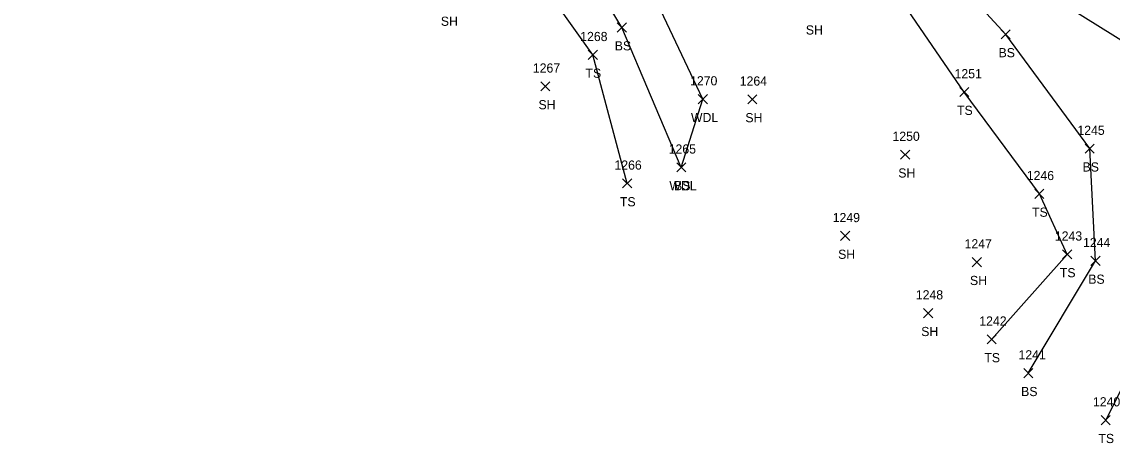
# Model space of a CAD drawing. Extents: x 1537342 to 1542195, y 163002 to 168596.
# Drawn here: x 1541701.1 to 1541938.8, y 163108.8 to 163200.7 of the extents above; entities that cross this region are included whole.
import ezdxf

# ---------------------------------------------------------------- set-up
doc = ezdxf.new("R2010")
doc.units = 0
for name, color, linetype in [('L_A', 7, 'Continuous'), ('L_I', 7, 'Continuous'), ('L_TIC', 7, 'Continuous'), ('LAWA', 7, 'Continuous'), ('LELB', 7, 'Continuous')]:
    doc.layers.add(name, color=color, linetype=linetype)

msp = doc.modelspace()

# ---------------------------------------------------------------- linework, layer by layer
at = {"layer": 'L_TIC'}
for points in [[(1541830.91, 163198.44), (1541832.91, 163200.44)], [(1541832.91, 163198.44), (1541830.91, 163200.44)], [(1541914.6, 163196.94), (1541916.6, 163198.94)], [(1541916.6, 163196.94), (1541914.6, 163198.94)], [(1541824.57, 163192.47), (1541826.57, 163194.47)], [(1541826.57, 163192.47), (1541824.57, 163194.47)], [(1541814.24, 163185.6), (1541816.24, 163187.6)], [(1541816.24, 163185.6), (1541814.24, 163187.6)], [(1541848.55, 163182.81), (1541850.55, 163184.81)], [(1541850.55, 163182.81), (1541848.55, 163184.81)], [(1541859.35, 163182.77), (1541861.35, 163184.77)], [(1541861.35, 163182.77), (1541859.35, 163184.77)], [(1541905.57, 163184.36), (1541907.57, 163186.36)], [(1541907.57, 163184.36), (1541905.57, 163186.36)], [(1541932.92, 163172.02), (1541934.92, 163174.02)], [(1541934.92, 163172.02), (1541932.92, 163174.02)], [(1541892.69, 163170.71), (1541894.69, 163172.71)], [(1541894.69, 163170.71), (1541892.69, 163172.71)], [(1541843.86, 163167.93), (1541845.86, 163169.93)], [(1541845.86, 163167.93), (1541843.86, 163169.93)], [(1541843.86, 163167.93), (1541845.86, 163169.93)], [(1541845.86, 163167.93), (1541843.86, 163169.93)], [(1541832.08, 163164.43), (1541834.08, 163166.43)], [(1541834.08, 163164.43), (1541832.08, 163166.43)], [(1541921.93, 163162.15), (1541923.93, 163164.15)], [(1541923.93, 163162.15), (1541921.93, 163164.15)], [(1541879.58, 163152.98), (1541881.58, 163154.98)], [(1541881.58, 163152.98), (1541879.58, 163154.98)], [(1541908.32, 163147.26), (1541910.32, 163149.26)], [(1541910.32, 163147.26), (1541908.32, 163149.26)], [(1541928, 163148.96), (1541930, 163150.96)], [(1541930, 163148.96), (1541928, 163150.96)], [(1541934.16, 163147.54), (1541936.16, 163149.54)], [(1541936.16, 163147.54), (1541934.16, 163149.54)], [(1541897.69, 163136.13), (1541899.69, 163138.13)], [(1541899.69, 163136.13), (1541897.69, 163138.13)], [(1541911.53, 163130.42), (1541913.53, 163132.42)], [(1541913.53, 163130.42), (1541911.53, 163132.42)], [(1541919.52, 163123.04), (1541921.52, 163125.04)], [(1541921.52, 163123.04), (1541919.52, 163125.04)], [(1541936.4, 163112.8), (1541938.4, 163114.8)], [(1541938.4, 163112.8), (1541936.4, 163114.8)]]:
    msp.add_lwpolyline(points, dxfattribs=at)
at = {"layer": 'LAWA'}
msp.add_lwpolyline([(1541844.86, 163168.93), (1541849.55, 163183.81), (1541839.11, 163205.97), (1541817.65, 163223.23), (1541815, 163239.81), (1541816.56, 163255.64), (1541792.4, 163274.28), (1541779.24, 163270.52), (1541762.88, 163259.76), (1541752.39, 163275.43), (1541738.68, 163268.21), (1541722.17, 163262.13), (1541701.08, 163257.12)], dxfattribs=at)
at = {"layer": 'LELB'}
for points in [[(1541982.35, 163154.54), (1541977.46, 163162.71), (1541976.49, 163171.88), (1541973.52, 163173.98), (1541972.19, 163175.21), (1541955.89, 163187.24), (1541919.33, 163210.02), (1541893.74, 163229.08), (1541863.64, 163247.96), (1541848.89, 163252.66), (1541830.96, 163271.76), (1541807.53, 163290.35), (1541793.3, 163299.34), (1541792.63, 163303.62)], [(1541920.52, 163124.04), (1541935.16, 163148.54), (1541933.92, 163173.02), (1541915.6, 163197.94), (1541891.22, 163224.52), (1541851.87, 163246.31), (1541828.99, 163268.29), (1541806.16, 163287.41), (1541789.02, 163298.58), (1541787.18, 163300.8)], [(1541912.53, 163131.42), (1541929, 163149.96), (1541922.93, 163163.15), (1541906.57, 163185.36), (1541883.88, 163218.47), (1541847.29, 163243.18), (1541824.83, 163266.16), (1541803.8, 163284.14), (1541786.25, 163296.89)], [(1541844.86, 163168.93), (1541831.91, 163199.44), (1541817.65, 163223.23), (1541791.64, 163233.2), (1541773.3, 163225.27), (1541742.38, 163225.52), (1541715.33, 163231.42)], [(1541833.08, 163165.43), (1541825.57, 163193.47), (1541808.98, 163216.83), (1541792.66, 163223.09), (1541778.15, 163217.47), (1541745.19, 163221.24), (1541715.02, 163221.12)], [(1541972.19, 163175.21), (1541970.62, 163165.38), (1541967.08, 163155.79), (1541951, 163141.2), (1541937.4, 163113.8)]]:
    msp.add_lwpolyline(points, dxfattribs=at)

# ---------------------------------------------------------------- texts
at = {"layer": 'L_A'}
for s, p in [('SH', (1541792.44, 163199.8)), ('SH', (1541872.02, 163197.9)), ('BS', (1541830.36, 163194.44)), ('BS', (1541914.04, 163192.94)), ('TS', (1541823.98, 163188.47)), ('SH', (1541813.73, 163181.6)), ('TS', (1541904.98, 163180.36)), ('WDL', (1541846.97, 163178.81)), ('SH', (1541858.84, 163178.77)), ('SH', (1541892.18, 163166.71)), ('BS', (1541932.36, 163168.02)), ('WDL', (1541842.27, 163163.93)), ('BS', (1541843.3, 163163.93)), ('TS', (1541831.49, 163160.43)), ('TS', (1541921.34, 163158.15)), ('SH', (1541879.06, 163148.98)), ('TS', (1541927.41, 163144.96)), ('SH', (1541907.81, 163143.26)), ('BS', (1541933.6, 163143.54)), ('SH', (1541897.18, 163132.13)), ('TS', (1541910.94, 163126.42)), ('BS', (1541918.96, 163119.04)), ('TS', (1541935.81, 163108.8))]:
    msp.add_text(s, height=2, dxfattribs=at).set_placement(p)
at = {"layer": 'L_I'}
for s, p in [('1268', (1541822.83, 163196.47)), ('1267', (1541812.5, 163189.6)), ('1251', (1541904.45, 163188.36)), ('1270', (1541846.78, 163186.81)), ('1264', (1541857.61, 163186.77)), ('1245', (1541931.23, 163176.02)), ('1250', (1541890.91, 163174.71)), ('1265', (1541842.12, 163171.93)), ('1265', (1541842.12, 163171.93)), ('1266', (1541830.29, 163168.43)), ('1246', (1541920.19, 163166.15)), ('1249', (1541877.88, 163156.98)), ('1243', (1541926.31, 163152.96)), ('1247', (1541906.63, 163151.26)), ('1244', (1541932.46, 163151.54)), ('1248', (1541896, 163140.13)), ('1242', (1541909.84, 163134.42)), ('1241', (1541918.39, 163127.04)), ('1240', (1541934.62, 163116.8))]:
    msp.add_text(s, height=2, dxfattribs=at).set_placement(p)

doc.saveas('drawing.dxf')
